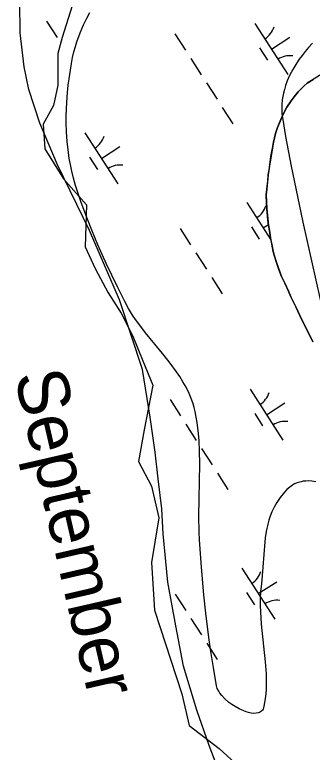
# Model space of a CAD drawing. Extents: x 3937982 to 3958556, y 219448 to 241894.
# Drawn here: x 3949683 to 3949928, y 228394 to 229001 of the extents above; entities that cross this region are included whole.
import ezdxf

# ---------------------------------------------------------------- set-up
doc = ezdxf.new("R2010")
doc.units = 0
for name, color, linetype in [('V-RIVR-EDGE', 7, 'Continuous'), ('V-RIVR-IDEN', 7, 'Continuous'), ('V-SITE-VEGE', 7, 'Continuous'), ('V-TOPO-SHOR', 7, 'Continuous'), ('V-WETL-SWMP', 7, 'Continuous')]:
    doc.layers.add(name, color=color, linetype=linetype)

msp = doc.modelspace()

# ---------------------------------------------------------------- linework, layer by layer
at = {"layer": 'V-RIVR-EDGE'}
msp.add_lwpolyline([(3949729.983, 229008.74), (3949721.673, 228982.622), (3949718.111, 228969.562), (3949718.111, 228943.444), (3949714.549, 228926.823), (3949706.239, 228911.389), (3949707.426, 228891.206), (3949722.86, 228866.275), (3949741.855, 228844.905), (3949740.668, 228810.476), (3949748.979, 228792.668), (3949759.664, 228772.485), (3949770.348, 228755.864), (3949779.846, 228736.869), (3949788.157, 228716.686), (3949796.467, 228696.503), (3949789.344, 228659.7), (3949784.595, 228633.581), (3949795.28, 228613.398), (3949801.216, 228587.28), (3949795.28, 228550.476), (3949797.654, 228511.298), (3949820.211, 228442.44), (3949826.147, 228416.321), (3949851.079, 228397.326), (3949864.138, 228385.454)], dxfattribs=at)
at = {"layer": 'V-SITE-VEGE'}
for points in [[(3949815.863, 228707.556), (3949810.581, 228714.745), (3949805.703, 228720.923), (3949790.322, 228739.708), (3949785.575, 228745.864), (3949782.177, 228750.564), (3949779.744, 228754.152), (3949776.334, 228759.649), (3949773.25, 228765.314), (3949767.467, 228776.944), (3949762.529, 228787.176), (3949758.316, 228796.175), (3949751.234, 228812.047), (3949746.2, 228824.067), (3949742.604, 228833.156), (3949737.523, 228846.912), (3949732.857, 228860.841), (3949731.084, 228866.888), (3949729.648, 228872.623), (3949728.495, 228878.048), (3949727.582, 228883.172), (3949726.863, 228888.007), (3949725.864, 228897.135), (3949725.345, 228905.176), (3949725.149, 228912.235), (3949725.159, 228918.42), (3949725.571, 228929.244), (3949726.179, 228937.338), (3949726.791, 228943.383), (3949727.942, 228952.392), (3949729.345, 228961.309), (3949730.326, 228966.325), (3949731.446, 228970.974), (3949732.663, 228975.287), (3949733.943, 228979.289), (3949736.675, 228986.694), (3949739.397, 228993.074), (3949742.01, 228998.579), (3949744.449, 229003.343)], [(3949927.819, 228978.181), (3949924.556, 228974.597), (3949921.665, 228971.187), (3949919.107, 228967.945), (3949916.848, 228964.873), (3949914.861, 228961.955), (3949911.486, 228956.411), (3949908.934, 228951.479), (3949907.021, 228947.104), (3949905.604, 228943.236), (3949904.57, 228939.82), (3949903.827, 228936.805), (3949902.903, 228931.484), (3949902.534, 228927.458), (3949902.448, 228924.415), (3949902.633, 228919.821), (3949903.204, 228915.193), (3949905.623, 228901.199), (3949910.255, 228876.688), (3949914.001, 228858.299), (3949919.92, 228830.727), (3949937.713, 228751.224)], [(3949930.543, 228617.061), (3949927.334, 228617.499), (3949924.556, 228617.659), (3949922.158, 228617.606), (3949920.092, 228617.393), (3949918.306, 228617.067), (3949915.248, 228616.168), (3949913.02, 228615.191), (3949911.388, 228614.274), (3949909.008, 228612.584), (3949906.718, 228610.493), (3949904.687, 228608.312), (3949901.236, 228604.071), (3949898.43, 228599.944), (3949896.194, 228596.004), (3949894.412, 228592.256), (3949892.995, 228588.696), (3949891.866, 228585.327), (3949890.967, 228582.139), (3949889.648, 228576.099), (3949888.815, 228570.764), (3949885.644, 228533.085), (3949884.971, 228526.785), (3949884.688, 228520.803), (3949884.682, 228515.142), (3949884.87, 228509.795), (3949885.608, 228499.698), (3949888.911, 228468.749), (3949889.568, 228458.98), (3949889.712, 228451.769), (3949889.564, 228446.442), (3949889.282, 228442.496), (3949888.551, 228436.669), (3949887.4, 228430.97), (3949887.017, 228429.833), (3949886.488, 228428.895), (3949885.841, 228428.133), (3949885.094, 228427.531), (3949884.268, 228427.064), (3949883.373, 228426.724), (3949881.417, 228426.36), (3949879.345, 228426.345), (3949877.235, 228426.601), (3949875.136, 228427.064), (3949873.09, 228427.674), (3949871.122, 228428.395), (3949867.37, 228430.091), (3949864.104, 228431.895), (3949861.329, 228433.687), (3949859.006, 228435.389), (3949855.516, 228438.4), (3949853.063, 228441.005), (3949851.512, 228443.01), (3949850.538, 228444.533), (3949849.424, 228446.819), (3949848.764, 228449.086), (3949846.171, 228464.078), (3949844.134, 228477.199), (3949842.516, 228488.684), (3949840.027, 228508.798), (3949838.42, 228523.898), (3949836.378, 228546.583), (3949834.715, 228569.318), (3949834.379, 228575.902), (3949834.174, 228588.274), (3949835.018, 228631.651), (3949834.862, 228642.471), (3949834.469, 228650.566), (3949833.975, 228656.626), (3949832.857, 228665.695), (3949832.102, 228670.213), (3949831.202, 228674.727), (3949830.412, 228678.012), (3949829.501, 228681.131), (3949828.495, 228684.09), (3949826.224, 228689.679), (3949823.744, 228694.758), (3949821.145, 228699.393), (3949818.501, 228703.644), (3949815.863, 228707.556)]]:
    msp.add_lwpolyline(points, dxfattribs=at)
at = {"layer": 'V-TOPO-SHOR'}
msp.add_lwpolyline([(3949927.991, 228732.181), (3949924.894, 228738.561), (3949921.929, 228744.299), (3949920.123, 228748.127), (3949917.413, 228753.74), (3949915.609, 228757.312), (3949913.931, 228761.013), (3949912.254, 228764.458), (3949909.805, 228769.305), (3949907.865, 228774.026), (3949904.898, 228780.532), (3949902.317, 228785.892), (3949900.12, 228791.635), (3949898.049, 228797.379), (3949896.233, 228803.509), (3949895.452, 228806.446), (3949894.799, 228809.51), (3949893.886, 228814.236), (3949893.23, 228817.556), (3949892.573, 228822.156), (3949891.522, 228828.29), (3949891.123, 228832.251), (3949890.723, 228835.699), (3949890.06, 228841.577), (3949889.912, 228846.179), (3949889.755, 228853.083), (3949890.115, 228857.943), (3949890.855, 228864.849), (3949891.344, 228869.582), (3949891.965, 228873.929), (3949892.833, 228880.454), (3949893.58, 228884.804), (3949894.701, 228891.585), (3949895.702, 228896.447), (3949897.332, 228903.74), (3949898.975, 228908.606), (3949901.758, 228915.266), (3949903.657, 228919.749), (3949906.702, 228925.258), (3949910.128, 228930.643), (3949912.545, 228933.85), (3949915.977, 228937.956), (3949918.396, 228940.522), (3949920.815, 228942.961), (3949923.362, 228945.147), (3949928.208, 228948.108)], dxfattribs=at)
at = {"layer": 'V-WETL-SWMP'}
for p, q in [((3949708.95, 228996.204), (3949717.61, 228982.75)), ((3949880.402, 228994.272), (3949907.465, 228952.229)), ((3949814.537, 228985.678), (3949823.197, 228972.224)), ((3949893.933, 228973.251), (3949909.069, 228982.993)), ((3949884.198, 228974.12), (3949890.693, 228964.03)), ((3949827.527, 228965.497), (3949836.187, 228952.043)), ((3949840.517, 228945.316), (3949849.177, 228931.862)), ((3949853.507, 228925.135), (3949862.167, 228911.681)), ((3949740.535, 228904.243), (3949767.597, 228862.2)), ((3949754.066, 228883.221), (3949769.202, 228892.964)), ((3949744.331, 228884.091), (3949750.826, 228874)), ((3949873.664, 228846.944), (3949893.514, 228816.107)), ((3949887.195, 228825.923), (3949891.48, 228828.681)), ((3949818.798, 228825.547), (3949827.458, 228812.093)), ((3949877.46, 228826.792), (3949883.955, 228816.702)), ((3949831.788, 228805.367), (3949840.448, 228791.913)), ((3949844.778, 228785.186), (3949853.438, 228771.732)), ((3949876.363, 228693.225), (3949903.425, 228651.181)), ((3949810.498, 228684.63), (3949819.158, 228671.176)), ((3949889.894, 228672.203), (3949905.03, 228681.946)), ((3949880.159, 228673.072), (3949886.654, 228662.982)), ((3949823.488, 228664.449), (3949832.148, 228650.995)), ((3949836.478, 228644.268), (3949845.138, 228630.814)), ((3949849.468, 228624.088), (3949858.127, 228610.634)), ((3949869.625, 228545.897), (3949896.687, 228503.853)), ((3949883.156, 228524.875), (3949898.292, 228534.617)), ((3949814.759, 228524.5), (3949823.419, 228511.046)), ((3949873.421, 228525.744), (3949879.916, 228515.654)), ((3949827.749, 228504.319), (3949836.409, 228490.865)), ((3949840.739, 228484.138), (3949849.398, 228470.684))]:
    msp.add_line(p, q, dxfattribs=at)
for points in [[(3949842.815, 228399.857), (3949832.583, 228428.964), (3949821.544, 228465.065), (3949815.181, 228498.464), (3949808.807, 228534.196), (3949804.747, 228574.214), (3949803.881, 228594.811), (3949800.666, 228619.284), (3949798.238, 228641.429), (3949794.227, 228670.175), (3949787.838, 228709.405), (3949768.933, 228766.849), (3949744.199, 228823.88), (3949717.924, 228877.794), (3949703.393, 228912.325), (3949694.334, 228939.882), (3949690.367, 228958.522), (3949687.136, 228986.494), (3949687.027, 229011.758)], [(3949937.133, 228953.516), (3949923.362, 228945.147), (3949920.815, 228942.962), (3949918.396, 228940.523), (3949915.978, 228937.956), (3949912.544, 228933.85), (3949910.129, 228930.643), (3949906.701, 228925.259), (3949903.656, 228919.749), (3949898.974, 228908.606), (3949897.333, 228903.741), (3949895.703, 228896.447), (3949894.701, 228891.585), (3949892.832, 228880.454), (3949891.345, 228869.581), (3949890.116, 228857.942), (3949889.754, 228853.083), (3949890.059, 228841.578), (3949891.523, 228828.289), (3949892.572, 228822.157), (3949893.231, 228817.557), (3949894.8, 228809.51), (3949895.453, 228806.445), (3949896.232, 228803.508), (3949898.049, 228797.379), (3949902.317, 228785.892), (3949904.897, 228780.533), (3949907.866, 228774.026), (3949909.804, 228769.305), (3949913.931, 228761.013), (3949915.608, 228757.312), (3949917.414, 228753.741), (3949921.929, 228744.3), (3949924.894, 228738.56), (3949927.99, 228732.181)], [(3949854.61, 228368.812), (3949842.815, 228399.857)]]:
    msp.add_lwpolyline(points, dxfattribs=at)
for centre, start, end in [((3949879.183, 228996.605), 301.99668, 343.540338), ((3949909.083, 228950.153), 81.996677, 123.540335), ((3949739.316, 228906.576), 301.99668, 343.540338), ((3949769.216, 228860.124), 81.996677, 123.540335), ((3949872.445, 228849.277), 301.99668, 343.540338), ((3949902.345, 228802.825), 121.318297, 123.540335), ((3949875.144, 228695.557), 301.99668, 343.540338), ((3949905.044, 228649.106), 81.996677, 123.540335), ((3949868.406, 228548.229), 301.99668, 343.540338), ((3949898.306, 228501.778), 81.996677, 123.540335)]:
    msp.add_arc(centre, 17.623, start, end, dxfattribs=at)

# ---------------------------------------------------------------- texts
at = {"layer": 'V-RIVR-IDEN'}
msp.add_text('September', height=41.9999, rotation=282.964357, dxfattribs=at).set_placement((3949682.251, 228704.636))

doc.saveas('drawing.dxf')
